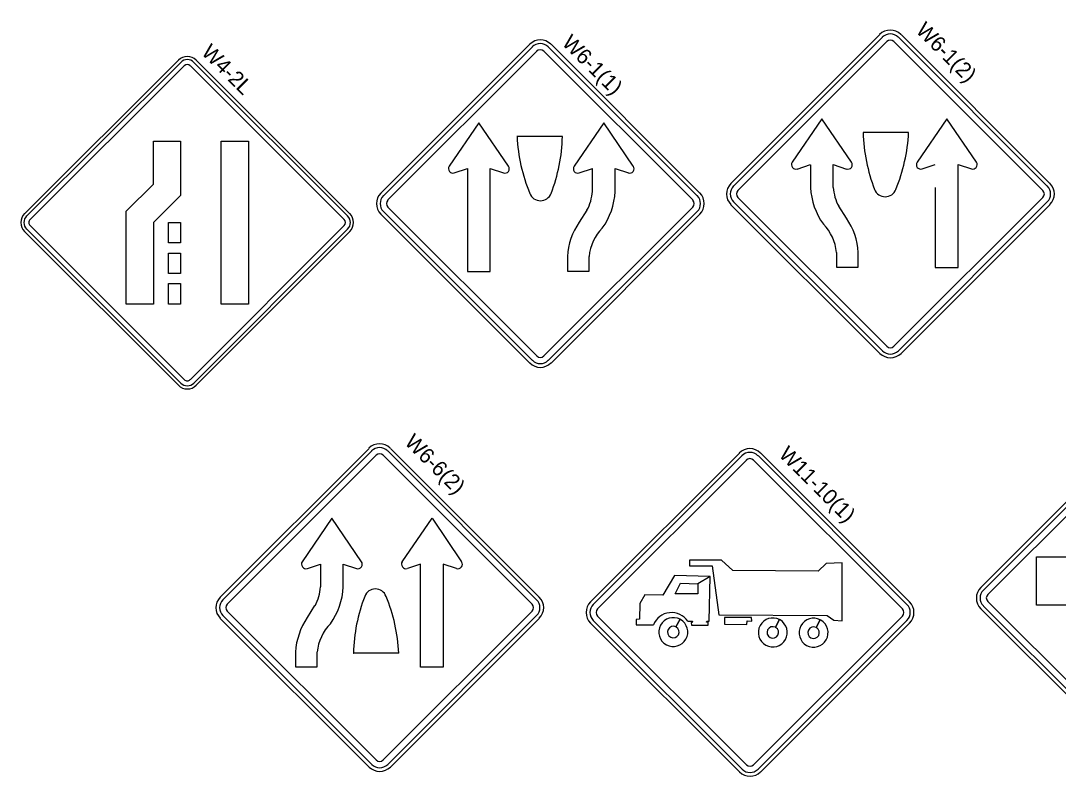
# Model space of a CAD drawing. Extents: x 1531.44 to 1538.58, y 1529.59 to 1539.3.
# Drawn here: x 1531.503 to 1535.575, y 1534.291 to 1537.259 of the extents above; entities that cross this region are included whole.
import ezdxf

# ---------------------------------------------------------------- set-up
doc = ezdxf.new("R2010")
doc.units = 0
for name, color, linetype in [('DETL-LINE', 7, 'Continuous'), ('DETL-NOTE', 7, 'Continuous'), ('SIGN-FACE_E', 7, 'Continuous')]:
    doc.layers.add(name, color=color, linetype=linetype)

msp = doc.modelspace()

# ---------------------------------------------------------------- linework, layer by layer
at = {"layer": 'DETL-LINE'}
for p, q in [((1534.8744, 1537.2042), (1534.2901, 1536.6198)), ((1534.885, 1537.1945), (1534.3007, 1536.6093)), ((1535.5318, 1536.6093), (1534.9475, 1537.1945)), ((1535.5424, 1536.6198), (1534.958, 1537.2042)), ((1533.5003, 1537.1663), (1532.916, 1536.582)), ((1533.5109, 1537.1566), (1532.9266, 1536.5714)), ((1534.1577, 1536.5714), (1533.5734, 1537.1566)), ((1534.1682, 1536.582), (1533.5839, 1537.1663)), ((1534.3174, 1536.5926), (1534.9026, 1537.1769)), ((1534.9294, 1537.1768), (1534.9299, 1537.1769)), ((1535.5142, 1536.5926), (1534.9299, 1537.1769)), ((1534.9299, 1537.1769), (1535.5142, 1536.5926)), ((1534.9299, 1537.1769), (1535.5142, 1536.5926)), ((1532.9433, 1536.5547), (1533.5285, 1537.139)), ((1533.5553, 1537.139), (1533.5558, 1537.139)), ((1534.1401, 1536.5547), (1533.5558, 1537.139)), ((1533.5558, 1537.139), (1534.1401, 1536.5547)), ((1533.5558, 1537.139), (1534.1401, 1536.5547)), ((1533.3007, 1536.8583), (1533.1846, 1536.6876)), ((1533.4169, 1536.6876), (1533.3007, 1536.8583)), ((1533.7909, 1536.8583), (1533.6747, 1536.6876)), ((1533.907, 1536.6876), (1533.7909, 1536.8583)), ((1534.6471, 1536.8741), (1534.531, 1536.7034)), ((1534.7633, 1536.7034), (1534.6471, 1536.8741)), ((1535.1373, 1536.8741), (1535.0211, 1536.7034)), ((1535.2534, 1536.7034), (1535.1373, 1536.8741)), ((1534.9877, 1536.8196), (1534.809, 1536.8196)), ((1533.629, 1536.8037), (1533.4503, 1536.8037)), ((1534.5503, 1536.6761), (1534.6022, 1536.6937)), ((1534.6022, 1536.6928), (1534.6022, 1536.604)), ((1534.692, 1536.6937), (1534.7439, 1536.6761)), ((1534.692, 1536.6928), (1534.692, 1536.6937)), ((1534.692, 1536.604), (1534.692, 1536.6928)), ((1535.0405, 1536.677), (1535.0924, 1536.6937)), ((1535.1822, 1536.604), (1535.1822, 1536.6937)), ((1535.1822, 1536.6937), (1535.2341, 1536.677)), ((1533.2039, 1536.6612), (1533.2558, 1536.6779)), ((1533.2558, 1536.6779), (1533.2558, 1536.5881)), ((1533.3456, 1536.5881), (1533.3456, 1536.6779)), ((1533.3456, 1536.6779), (1533.3975, 1536.6612)), ((1533.6941, 1536.6612), (1533.7469, 1536.6779)), ((1533.746, 1536.6779), (1533.746, 1536.5881)), ((1533.8358, 1536.6779), (1533.8877, 1536.6612)), ((1533.8358, 1536.5881), (1533.8358, 1536.6779)), ((1533.2558, 1536.5881), (1533.2558, 1536.2731)), ((1533.3456, 1536.2731), (1533.3456, 1536.5881)), ((1535.0924, 1536.604), (1535.0924, 1536.2889)), ((1535.1822, 1536.2889), (1535.1822, 1536.604)), ((1534.2901, 1536.5362), (1534.8744, 1535.9519)), ((1534.3007, 1536.5468), (1534.885, 1535.9625)), ((1534.9026, 1535.9801), (1534.3174, 1536.5644)), ((1534.7439, 1536.4834), (1534.7131, 1536.53)), ((1535.5142, 1536.5644), (1534.9299, 1535.9801)), ((1534.9475, 1535.9625), (1535.5318, 1536.5468)), ((1534.958, 1535.9519), (1535.5424, 1536.5362)), ((1532.916, 1536.4984), (1533.5003, 1535.9141)), ((1532.9266, 1536.509), (1533.5109, 1535.9246)), ((1533.5285, 1535.9422), (1532.9433, 1536.5266)), ((1534.1401, 1536.5266), (1533.5558, 1535.9422)), ((1533.5734, 1535.9246), (1534.1577, 1536.509)), ((1533.5839, 1535.9141), (1534.1682, 1536.4984)), ((1533.7249, 1536.5142), (1533.6941, 1536.4676)), ((1533.6483, 1536.3329), (1533.6483, 1536.2748)), ((1533.7337, 1536.2748), (1533.7337, 1536.3329)), ((1534.7043, 1536.3488), (1534.7043, 1536.2907)), ((1534.7897, 1536.2907), (1534.7897, 1536.3488)), ((1534.7043, 1536.2907), (1534.7897, 1536.2907)), ((1535.0924, 1536.2889), (1535.1822, 1536.2889)), ((1533.2558, 1536.2731), (1533.3456, 1536.2731)), ((1533.6483, 1536.2748), (1533.7337, 1536.2748)), ((1535.8551, 1535.6169), (1535.2708, 1535.0326)), ((1535.8657, 1535.6072), (1535.2814, 1535.022)), ((1532.87, 1535.579), (1532.2856, 1534.9947)), ((1532.8805, 1535.5694), (1532.2962, 1534.9842)), ((1532.3129, 1534.9674), (1532.8981, 1535.5518)), ((1532.925, 1535.5517), (1532.9254, 1535.5518)), ((1533.5097, 1534.9674), (1532.9254, 1535.5518)), ((1532.9254, 1535.5518), (1533.5097, 1534.9674)), ((1532.9254, 1535.5518), (1533.5097, 1534.9674)), ((1533.5273, 1534.9842), (1532.943, 1535.5694)), ((1533.5379, 1534.9947), (1532.9536, 1535.579)), ((1534.3234, 1535.5601), (1533.7391, 1534.9758)), ((1534.9914, 1534.9758), (1534.407, 1535.5601)), ((1535.2981, 1535.0053), (1535.8833, 1535.5896)), ((1534.334, 1535.5504), (1533.7497, 1534.9652)), ((1533.7664, 1534.9485), (1534.3516, 1535.5328)), ((1534.3784, 1535.5328), (1534.3789, 1535.5328)), ((1534.9632, 1534.9485), (1534.3789, 1535.5328)), ((1534.3789, 1535.5328), (1534.9632, 1534.9485)), ((1534.3789, 1535.5328), (1534.9632, 1534.9485)), ((1534.9808, 1534.9652), (1534.3965, 1535.5504)), ((1532.7234, 1535.3042), (1532.6073, 1535.1335)), ((1532.8405, 1535.1335), (1532.7234, 1535.3042)), ((1532.9998, 1535.1335), (1533.1168, 1535.3042)), ((1533.1168, 1535.3042), (1533.233, 1535.1335)), ((1535.4896, 1534.9628), (1535.4896, 1535.1523)), ((1535.4896, 1535.1523), (1535.6407, 1535.1523)), ((1532.6275, 1535.1071), (1532.6794, 1535.1238)), ((1532.6794, 1535.1238), (1532.6794, 1535.0349)), ((1532.7683, 1535.0349), (1532.7683, 1535.1238)), ((1532.7683, 1535.1238), (1532.8202, 1535.1071)), ((1532.8202, 1535.1071), (1532.8203, 1535.1072)), ((1533.0719, 1535.1238), (1533.02, 1535.1071)), ((1533.0719, 1535.0349), (1533.0719, 1535.1238)), ((1533.2127, 1535.1071), (1533.1608, 1535.1238)), ((1533.1608, 1535.1238), (1533.1608, 1535.0349)), ((1534.2529, 1535.14), (1534.128, 1535.14)), ((1534.128, 1535.14), (1534.128, 1535.1172)), ((1534.128, 1535.1172), (1534.216, 1535.1172)), ((1534.216, 1535.1172), (1534.243, 1534.9254)), ((1534.297, 1535.0988), (1534.2529, 1535.14)), ((1534.6633, 1535.1272), (1534.6321, 1535.0959)), ((1534.7272, 1535.1286), (1534.6633, 1535.1272)), ((1534.7272, 1534.9012), (1534.7272, 1535.1286)), ((1534.0683, 1535.0789), (1534.0229, 1535.0022)), ((1534.2089, 1535.076), (1534.0683, 1535.0789)), ((1534.2089, 1535.076), (1534.1606, 1535.0462)), ((1534.2046, 1534.8998), (1534.2089, 1535.076)), ((1534.6321, 1535.0959), (1534.297, 1535.0988)), ((1533.0719, 1534.7199), (1533.0719, 1535.0349)), ((1533.1608, 1535.0349), (1533.1608, 1534.7199)), ((1534.0712, 1535.0078), (1534.0925, 1535.049)), ((1534.0925, 1535.049), (1534.1606, 1535.0462)), ((1534.1606, 1535.0462), (1534.1606, 1535.0078)), ((1533.9519, 1535.0036), (1533.932, 1534.9695)), ((1534.0229, 1535.0022), (1533.9519, 1535.0036)), ((1534.1606, 1535.0078), (1534.0712, 1535.0078)), ((1532.6275, 1534.9144), (1532.6574, 1534.961)), ((1533.932, 1534.9695), (1533.9306, 1534.9084)), ((1535.2708, 1534.949), (1535.8551, 1534.3646)), ((1535.2814, 1534.9595), (1535.8657, 1534.3752)), ((1535.8833, 1534.3928), (1535.2981, 1534.9771)), ((1535.6407, 1534.9628), (1535.4896, 1534.9628)), ((1532.2856, 1534.9111), (1532.87, 1534.3268)), ((1532.2962, 1534.9217), (1532.8805, 1534.3374)), ((1532.8981, 1534.355), (1532.3129, 1534.9393)), ((1533.5097, 1534.9393), (1532.9254, 1534.355)), ((1532.943, 1534.3374), (1533.5273, 1534.9217)), ((1532.9536, 1534.3268), (1533.5379, 1534.9111)), ((1533.7497, 1534.9027), (1534.334, 1534.3184)), ((1534.3516, 1534.336), (1533.7664, 1534.9203)), ((1533.9306, 1534.9084), (1533.9178, 1534.907)), ((1533.9178, 1534.907), (1533.9178, 1534.8856)), ((1534.0741, 1534.8776), (1534.0906, 1534.9074)), ((1534.0906, 1534.9074), (1534.0741, 1534.8776)), ((1534.0924, 1534.9064), (1534.0906, 1534.9074)), ((1534.1208, 1534.8998), (1534.1393, 1534.8998)), ((1534.1393, 1534.8998), (1534.1379, 1534.8942)), ((1534.1947, 1534.8956), (1534.1961, 1534.8998)), ((1534.1961, 1534.8998), (1534.2046, 1534.8998)), ((1534.243, 1534.9254), (1534.6676, 1534.9226)), ((1534.3708, 1534.914), (1534.2643, 1534.914)), ((1534.2643, 1534.914), (1534.2643, 1534.8885)), ((1534.3523, 1534.887), (1534.3538, 1534.9012)), ((1534.3538, 1534.9012), (1534.3722, 1534.8998)), ((1534.3722, 1534.8998), (1534.3708, 1534.914)), ((1534.9632, 1534.9203), (1534.3789, 1534.336)), ((1534.3965, 1534.3184), (1534.9808, 1534.9027)), ((1534.4646, 1534.8762), (1534.481, 1534.9061)), ((1534.481, 1534.9061), (1534.4646, 1534.8762)), ((1534.4829, 1534.905), (1534.481, 1534.9061)), ((1534.6245, 1534.8752), (1534.641, 1534.9051)), ((1534.641, 1534.9051), (1534.6245, 1534.8752)), ((1534.6428, 1534.904), (1534.641, 1534.9051)), ((1534.6676, 1534.9226), (1534.6946, 1534.9041)), ((1534.6946, 1534.9041), (1534.7272, 1534.9012)), ((1533.7391, 1534.8922), (1534.3234, 1534.3078)), ((1533.9178, 1534.8856), (1533.9857, 1534.8856)), ((1534.0741, 1534.8776), (1534.075, 1534.8771)), ((1534.1379, 1534.8942), (1534.1336, 1534.8942)), ((1534.1336, 1534.8942), (1534.1351, 1534.8842)), ((1534.1351, 1534.8842), (1534.2004, 1534.8842)), ((1534.2004, 1534.8956), (1534.1947, 1534.8956)), ((1534.2004, 1534.8842), (1534.2004, 1534.8956)), ((1534.2643, 1534.8885), (1534.3523, 1534.887)), ((1534.407, 1534.3078), (1534.9914, 1534.8922)), ((1534.4646, 1534.8762), (1534.4655, 1534.8758)), ((1534.6245, 1534.8752), (1534.6254, 1534.8748)), ((1532.5809, 1534.7788), (1532.5809, 1534.7208)), ((1532.6662, 1534.7208), (1532.6662, 1534.7788)), ((1532.8079, 1534.7744), (1532.8083, 1534.7748)), ((1532.9866, 1534.7744), (1532.8079, 1534.7744)), ((1532.5809, 1534.7208), (1532.6662, 1534.7208)), ((1533.1608, 1534.7199), (1533.0719, 1534.7199))]:
    msp.add_line(p, q, dxfattribs=at)
for centre, radius, start, end in [((1534.9155, 1537.1629), 0.059, 45, 135), ((1533.542, 1537.1246), 0.059, 45, 135), ((1534.9155, 1537.1629), 0.0443, 45, 135), ((1534.9155, 1537.1629), 0.0197, 45, 135), ((1533.5414, 1537.1251), 0.0443, 45, 135), ((1533.5414, 1537.1251), 0.0197, 45, 135), ((1535.4775, 1536.8371), 0.6685, 181.524, 201.0959), ((1534.3198, 1536.8524), 0.6685, 337.4833, 357.1559), ((1534.1183, 1536.8368), 0.6685, 182.8441, 202.5167), ((1532.9606, 1536.8214), 0.6685, 338.9042, 358.476), ((1534.5452, 1536.6932), 0.0175, 145.7397, 288), ((1534.749, 1536.6932), 0.0175, 252, 34.2603), ((1535.0354, 1536.6934), 0.0175, 145.7397, 288), ((1535.2392, 1536.6934), 0.0175, 252, 34.2603), ((1533.1989, 1536.6776), 0.0175, 145.7397, 288), ((1533.4026, 1536.6776), 0.0175, 252, 34.2603), ((1533.6891, 1536.6776), 0.0175, 145.7397, 288), ((1533.8928, 1536.6776), 0.0175, 252, 34.2603), ((1534.3319, 1536.5781), 0.059, 135, 225), ((1535.5006, 1536.5784), 0.059, 315, 45), ((1532.9577, 1536.5403), 0.059, 135, 225), ((1532.9575, 1536.5405), 0.0443, 135, 225), ((1533.5425, 1536.5963), 0.0446, 200.3641, 339.6359), ((1533.5684, 1536.6003), 0.1784, 331.1838, 356.1678), ((1533.5684, 1536.6003), 0.2674, 324.1907, 357.4446), ((1534.1265, 1536.5405), 0.0443, 315, 45), ((1534.1265, 1536.5405), 0.059, 315, 45), ((1534.3317, 1536.5784), 0.0443, 135, 225), ((1534.3317, 1536.5784), 0.0197, 135, 225), ((1534.8697, 1536.616), 0.2674, 182.5554, 215.8093), ((1534.8697, 1536.616), 0.1784, 183.8322, 208.8162), ((1534.8956, 1536.6119), 0.0446, 200.3641, 339.6359), ((1535.5006, 1536.5784), 0.0197, 315, 45), ((1535.5006, 1536.5784), 0.0443, 315, 45), ((1532.9575, 1536.5405), 0.0197, 135, 225), ((1534.1265, 1536.5405), 0.0197, 315, 45), ((1533.9126, 1536.3172), 0.265, 145.3872, 176.6343), ((1534.5255, 1536.3328), 0.1797, 4.968, 44.8693), ((1534.5255, 1536.3328), 0.265, 3.3657, 34.6128), ((1533.9126, 1536.3172), 0.1797, 135.1307, 175.032), ((1534.9161, 1535.9939), 0.0443, 225, 315), ((1534.9161, 1535.9939), 0.0197, 225, 315), ((1533.542, 1535.9561), 0.0443, 225, 315), ((1533.542, 1535.9561), 0.0197, 225, 315), ((1534.9161, 1535.9939), 0.059, 225, 315), ((1533.542, 1535.9561), 0.059, 225, 315), ((1532.911, 1535.5378), 0.059, 45, 135), ((1532.911, 1535.5378), 0.0443, 45, 135), ((1532.911, 1535.5378), 0.0197, 45, 135), ((1534.3645, 1535.5188), 0.059, 45, 135), ((1534.3645, 1535.5188), 0.0443, 45, 135), ((1534.3645, 1535.5188), 0.0197, 45, 135), ((1532.6219, 1535.1238), 0.0175, 145.7397, 288), ((1532.8257, 1535.1238), 0.0175, 252, 34.2603), ((1533.0145, 1535.1238), 0.0175, 145.7397, 288), ((1533.2185, 1535.1236), 0.0175, 252, 34.2603), ((1532.5013, 1535.0466), 0.1784, 331.1838, 356.1678), ((1532.5013, 1535.0466), 0.2674, 324.1907, 357.4446), ((1532.8946, 1534.9821), 0.0446, 20.3641, 159.6359), ((1535.3125, 1534.9908), 0.059, 135, 225), ((1535.3123, 1534.9911), 0.0443, 135, 225), ((1532.3274, 1534.953), 0.059, 135, 225), ((1532.3272, 1534.9532), 0.0443, 135, 225), ((1533.4766, 1534.757), 0.6685, 158.9042, 178.476), ((1532.3188, 1534.7416), 0.6685, 2.8441, 22.5167), ((1533.4961, 1534.9532), 0.0443, 315, 45), ((1533.4961, 1534.9532), 0.059, 315, 45), ((1535.3123, 1534.9911), 0.0197, 135, 225), ((1532.3272, 1534.9532), 0.0197, 135, 225), ((1533.4961, 1534.9532), 0.0197, 315, 45), ((1533.7809, 1534.934), 0.059, 135, 225), ((1533.7807, 1534.9343), 0.0443, 135, 225), ((1533.7807, 1534.9343), 0.0197, 135, 225), ((1534.9496, 1534.9343), 0.0197, 315, 45), ((1534.9496, 1534.9343), 0.0443, 315, 45), ((1534.9496, 1534.9343), 0.059, 315, 45), ((1532.8454, 1534.7634), 0.265, 145.3872, 176.6343), ((1534.057, 1534.8572), 0.0767, 33.749, 158.2615), ((1534.0641, 1534.8572), 0.0568, 62.1761, 60.0342), ((1534.4545, 1534.8558), 0.0568, 62.1761, 60.0342), ((1534.6145, 1534.8548), 0.0568, 62.1761, 60.0342), ((1532.8454, 1534.7634), 0.1797, 135.1307, 175.032), ((1534.0641, 1534.8572), 0.0227, 63.7142, 61.2479), ((1534.4545, 1534.8558), 0.0227, 63.7142, 61.2479), ((1534.6145, 1534.8548), 0.0227, 63.7142, 61.2479), ((1532.9116, 1534.3688), 0.0443, 225, 315), ((1532.9116, 1534.3688), 0.0197, 225, 315), ((1534.3651, 1534.3498), 0.0197, 225, 315), ((1532.9116, 1534.3688), 0.059, 225, 315), ((1534.3651, 1534.3498), 0.059, 225, 315), ((1534.3651, 1534.3498), 0.0443, 225, 315)]:
    msp.add_arc(centre, radius, start, end, dxfattribs=at)
at = {"layer": 'SIGN-FACE_E'}
for p, q in [((1532.1214, 1537.1041), (1531.5169, 1536.5009)), ((1532.7944, 1536.5009), (1532.1912, 1537.1041)), ((1532.1303, 1537.0952), (1531.5258, 1536.492)), ((1532.1443, 1537.0812), (1531.5398, 1536.478)), ((1532.7716, 1536.478), (1532.1684, 1537.0812)), ((1532.7855, 1536.492), (1532.1823, 1537.0952)), ((1531.5398, 1536.4539), (1532.1443, 1535.8495)), ((1532.1684, 1535.8495), (1532.7716, 1536.4539)), ((1531.5169, 1536.431), (1532.1214, 1535.8266)), ((1531.5258, 1536.4399), (1532.1303, 1535.8355)), ((1532.1823, 1535.8355), (1532.7855, 1536.4399)), ((1532.1912, 1535.8266), (1532.7944, 1536.431))]:
    msp.add_line(p, q, dxfattribs=at)
for points in [[(1531.9163, 1536.5102), (1532.023, 1536.6168), (1532.023, 1536.786), (1532.1296, 1536.786), (1532.1296, 1536.5726), (1532.023, 1536.466), (1532.023, 1536.146), (1531.9163, 1536.146), (1531.9163, 1536.5102)], [(1532.2896, 1536.786), (1532.3963, 1536.786), (1532.3963, 1536.146), (1532.2896, 1536.146), (1532.2896, 1536.786)], [(1532.1296, 1536.386), (1532.083, 1536.386), (1532.083, 1536.466), (1532.1296, 1536.466), (1532.1296, 1536.386)], [(1532.1296, 1536.266), (1532.083, 1536.266), (1532.083, 1536.346), (1532.1296, 1536.346), (1532.1296, 1536.266)], [(1532.1296, 1536.146), (1532.083, 1536.146), (1532.083, 1536.226), (1532.1296, 1536.226), (1532.1296, 1536.146)]]:
    msp.add_lwpolyline(points, dxfattribs=at)
for centre, radius, start, end in [((1532.1563, 1537.0688), 0.0496, 45, 134.94), ((1532.1563, 1537.0696), 0.0365, 45, 134.94), ((1532.1563, 1537.0699), 0.0165, 45, 134.94), ((1531.5522, 1536.466), 0.0496, 134.9399, 225), ((1531.5514, 1536.466), 0.0365, 134.9399, 225), ((1532.7599, 1536.466), 0.0365, 315.0601, 45), ((1532.7592, 1536.466), 0.0496, 315.0601, 45), ((1531.5511, 1536.466), 0.0165, 134.9399, 225), ((1532.7602, 1536.466), 0.0165, 315.0601, 45), ((1532.1563, 1535.8608), 0.0165, 225, 315.06), ((1532.1563, 1535.8618), 0.0496, 225, 315.06), ((1532.1563, 1535.8611), 0.0365, 225, 315.06)]:
    msp.add_arc(centre, radius, start, end, dxfattribs=at)

# ---------------------------------------------------------------- texts
at = {"layer": 'DETL-NOTE'}
for s, p in [('W6-1(2)', (1535.0126, 1537.2167)), ('W6-1(1)', (1533.6232, 1537.1674)), ('W4-2L', (1532.208, 1537.1304)), ('W6-6(2)', (1533.0056, 1535.5989)), ('W11-10(1)', (1534.4744, 1535.5508))]:
    msp.add_text(s, height=0.06, rotation=315, dxfattribs=at).set_placement(p)

doc.saveas('drawing.dxf')
